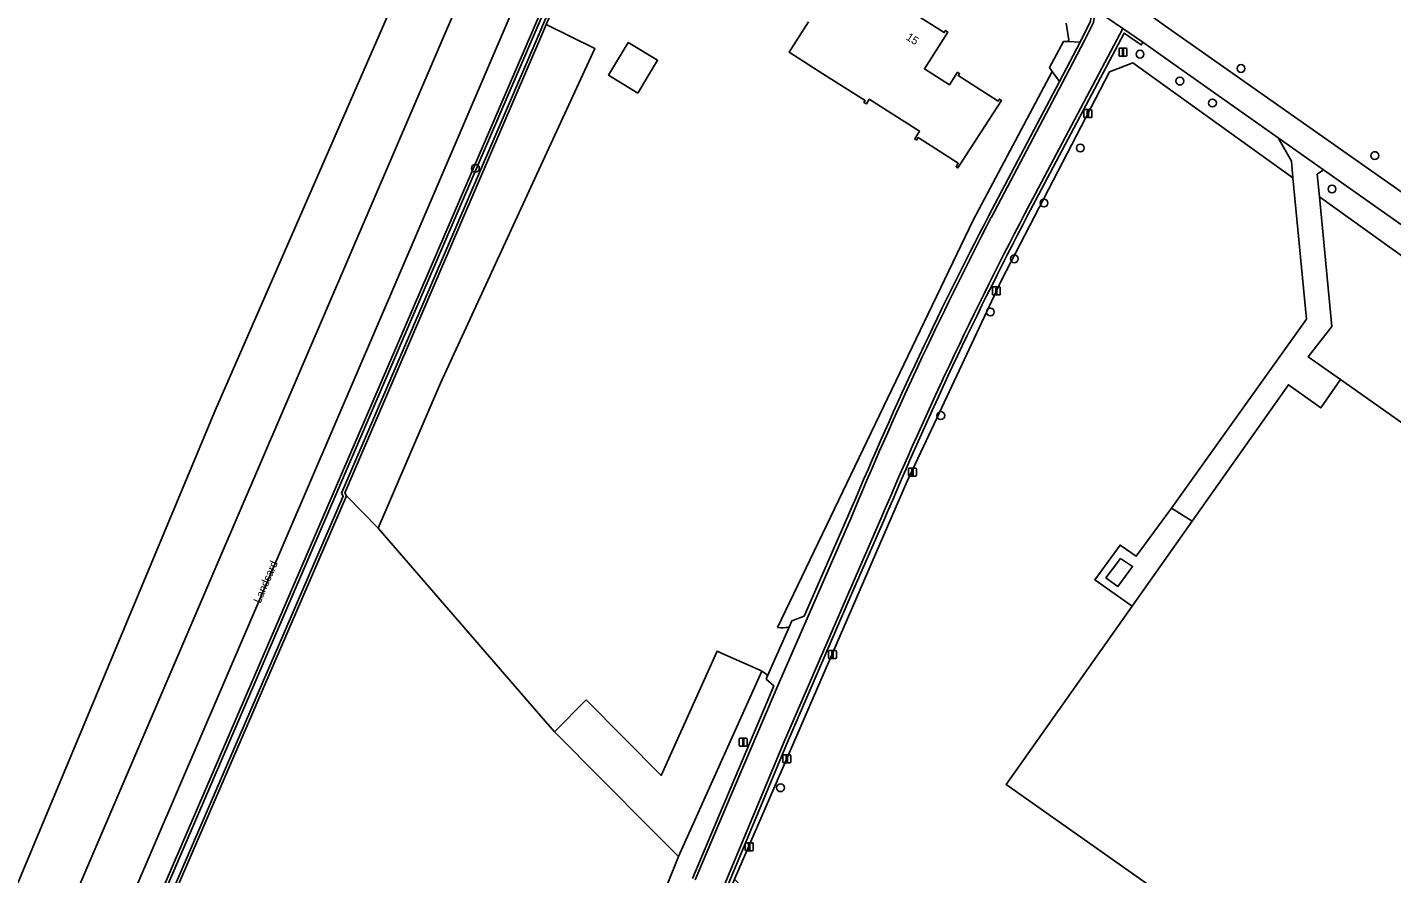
# Model space of a CAD drawing. Extents: x 155209 to 156748, y 385356 to 388487.
# Drawn here: x 155935.8 to 156106.4, y 386038.3 to 386144.1 of the extents above; entities that cross this region are included whole.
import ezdxf

# ---------------------------------------------------------------- set-up
doc = ezdxf.new("R2010")
doc.units = 0
for name, color, linetype in [('IMGEO_Berm_groen', 7, 'Continuous'), ('IMGEO_Berm_open', 7, 'Continuous'), ('IMGEO_Boom', 7, 'Continuous'), ('IMGEO_Erf', 7, 'Continuous'), ('IMGEO_Groenvoorziening', 7, 'Continuous'), ('IMGEO_Hek', 7, 'Continuous'), ('IMGEO_Lage_trafo', 7, 'Continuous'), ('IMGEO_Lichtmast', 7, 'Continuous'), ('IMGEO_Loofbos', 7, 'Continuous'), ('IMGEO_Naaldbos', 7, 'Continuous'), ('IMGEO_Oever', 7, 'Continuous'), ('IMGEO_Openbare_ruimte_label', 7, 'Continuous'), ('IMGEO_Pand', 7, 'Continuous'), ('IMGEO_Pand_nummerreeks', 7, 'Continuous'), ('IMGEO_Parkeervlak_gesloten', 7, 'Continuous'), ('IMGEO_Rijbaan_lokaal_gesloten', 7, 'Continuous'), ('IMGEO_Rijbaan_lokaal_open', 7, 'Continuous'), ('IMGEO_Verkeersbordpaal', 7, 'Continuous'), ('IMGEO_Voetpad_halfverhard', 7, 'Continuous'), ('IMGEO_Voetpad_open', 7, 'Continuous'), ('IMGEO_Waterloop', 7, 'Continuous')]:
    doc.layers.add(name, color=color, linetype=linetype)

msp = doc.modelspace()

# ---------------------------------------------------------------- linework, layer by layer
at = {"layer": 'IMGEO_Berm_groen'}
for points in [[(156017.72, 386241.8), (155997.34, 386192.47), (155999.28, 386187.65), (155999.02, 386187.05), (155959.3, 386096.17), (155916.98, 385994.93), (155916.27, 385993.23), (155920.08, 385991.51), (155920.81, 385993.21), (155925.38, 386003.82), (155927.74, 386002.82), (155959.53, 386076.88), (155989.7, 386147.22), (156003.54, 386179.53)], [(156049.55, 386158.86), (156049.35, 386159.56), (156025.31, 386175.19), (156018.61, 386179.53), (156012.19, 386182.98), (156009.84, 386177.42), (156009.58, 386176.82), (155984.91, 386119.23), (155965.64, 386074.34), (155949.14, 386035.92), (155952.02, 386034.68), (156000, 386146)], [(156065.66, 386144.59), (156066.01, 386142.46), (156065.9, 386142.27), (156067.43, 386142.22), (156068.71, 386144.84), (156068.81, 386145.67), (156068.51, 386146.37), (156067.67, 386146.89), (156067.9, 386147.28), (156055.22, 386155.8)], [(156078.71, 386139.75), (156075.27, 386142.2), (156075.05, 386141.86), (156072.94, 386143.34), (156062.21, 386123.11)], [(156018.62, 386023.35), (156020.7, 386028.43), (156024.22, 386037.59), (156045.81, 386087.34), (156049.5, 386095.21), (156057.59, 386112.46), (156071.11, 386138.48), (156074.02, 386139.6), (156094.02, 386125.25), (156093.82, 386127.35), (156092.18, 386130.24), (156078.71, 386139.75)], [(156135.52, 386099.82), (156125.95, 386106.41), (156097.82, 386126.26), (156097.06, 386125.69), (156097.33, 386122.88), (156148.23, 386086.38)], [(156042.89, 386082.44), (156038.86, 386073.22), (156030.85, 386054.72), (156018.71, 386025.67)], [(156027.62, 386063.6), (156017.22, 386040.43), (155993.88, 385981.94), (155984.26, 385961.78), (155979.58, 385953.33), (155982.07, 385950.57), (155982.25, 385950.72)], [(156018.96, 386037.69), (156023.47, 386048.35), (156027.93, 386058.88), (156029.15, 386061.75), (156028.19, 386062.62), (156028.36, 386063)]]:
    msp.add_lwpolyline(points, dxfattribs=at)
for centre, radius, start, end in [((156497.69, 385891.37), 493.3, 151.9805, 157.2124), ((156026.48, 386061.45), 2.44, 39.5677, 61.9809)]:
    msp.add_arc(centre, radius, start, end, dxfattribs=at)
at = {"layer": 'IMGEO_Berm_open'}
for points in [[(156056.32, 386120.34), (156065.18, 386137.08), (156067.96, 386142.42), (156069.08, 386144.68), (156069.24, 386145.9), (156068.86, 386146.59), (156067.9, 386147.28), (156067.67, 386146.89), (156068.51, 386146.37), (156068.81, 386145.67), (156068.71, 386144.84), (156067.43, 386142.22), (156064.83, 386137.29), (156056, 386120.53)], [(156075.27, 386142.2), (156072.75, 386143.92), (156061.83, 386123.29)], [(156062.21, 386123.11), (156072.94, 386143.34), (156075.05, 386141.86), (156075.27, 386142.2)], [(156042.51, 386082.62), (156038.47, 386073.36), (156030.47, 386054.89), (156018.34, 386025.82)], [(156018.71, 386025.67), (156030.85, 386054.72), (156038.86, 386073.22), (156042.89, 386082.44)], [(156038.35, 386082.83), (156032.91, 386070.46), (156031.37, 386069.88), (156031.03, 386069.11), (156028.36, 386063), (156028.19, 386062.62), (156029.15, 386061.75), (156027.93, 386058.88), (156023.47, 386048.35), (156018.96, 386037.69)], [(156029.56, 386061.6), (156038.74, 386082.69)], [(156019.32, 386037.52), (156023.82, 386048.16), (156029.56, 386061.6)]]:
    msp.add_lwpolyline(points, dxfattribs=at)
for centre, radius, start, end in [((156513.1, 385884.08), 510.75, 152.0725, 157.1251), ((156497.69, 385891.37), 493.3, 151.9805, 157.2124), ((156497.11, 385891.09), 497.21, 152.5191, 157.317), ((156504.59, 385888.19), 504.82, 152.6219, 157.3392)]:
    msp.add_arc(centre, radius, start, end, dxfattribs=at)
at = {"layer": 'IMGEO_Boom'}
for centre in [(156074.9, 386140.7), (156079.88, 386137.34), (156087.53, 386138.91), (156083.96, 386134.6), (156067.44, 386128.98), (156104.25, 386128.03), (155991.83, 386126.43), (156098.9, 386123.85), (156062.9, 386122.1), (156059.19, 386115.13), (156056.2, 386108.48), (156050, 386095.54), (156029.97, 386049.03)]:
    msp.add_circle(centre, 0.489, dxfattribs=at)
at = {"layer": 'IMGEO_Erf'}
for points in [[(156045.47, 386146.54), (156050.43, 386143.39), (156050.59, 386143.64), (156050.87, 386143.46), (156047.95, 386138.87), (156051.1, 386136.88), (156052.11, 386138.44), (156052.35, 386138.26), (156052.19, 386138.03), (156057.17, 386134.82), (156057.34, 386135.08), (156057.57, 386134.92), (156052.15, 386126.49), (156051.91, 386126.63), (156052.18, 386127.07), (156047.16, 386130.28), (156046.96, 386129.97), (156046.74, 386130.11), (156047.35, 386131.07), (156041.05, 386135.06), (156040.7, 386134.49), (156040.39, 386134.68), (156040.54, 386134.91), (156035.27, 386138.26), (156031.05, 386140.94), (156033.46, 386144.75)], [(156054.04, 386119.95), (156063.93, 386138.54), (156063.57, 386139.03), (156065.32, 386142.28), (156065.9, 386142.27), (156066.01, 386142.46), (156065.66, 386144.59)], [(156000.68, 386144.39), (156006.74, 386141.43), (156000, 386126.8), (155987.48, 386099.58), (155979.68, 386081.47), (156000, 386057.99), (156001.7, 386056.03), (156005.69, 386060.01), (156015.07, 386050.58), (156022.04, 386066.11), (156023.06, 386065.65), (156027.21, 386063.79), (156027.62, 386063.6)], [(156029.6, 386069.06), (156054.04, 386119.95)], [(156028.36, 386063), (156031.03, 386069.11)]]:
    msp.add_lwpolyline(points, dxfattribs=at)
msp.add_lwpolyline([(156012.13, 386135.85), (156008.47, 386138.07), (156010.94, 386142.15), (156014.6, 386139.94)], close=True, dxfattribs=at)
for centre, radius, start, end in [((156030.19, 386072.38), 3.37, 259.8828, 284.4364), ((156026.48, 386061.45), 2.44, 39.5677, 61.9809)]:
    msp.add_arc(centre, radius, start, end, dxfattribs=at)
at = {"layer": 'IMGEO_Groenvoorziening'}
for points in [[(156064.83, 386137.29), (156063.93, 386138.54), (156054.04, 386119.95), (156029.6, 386069.06)], [(156056, 386120.53), (156064.83, 386137.29)], [(156031.03, 386069.11), (156031.37, 386069.88), (156032.91, 386070.46), (156038.35, 386082.83)]]:
    msp.add_lwpolyline(points, dxfattribs=at)
for centre, radius, start, end in [((156497.11, 385891.09), 497.21, 152.5191, 157.317), ((156030.19, 386072.38), 3.37, 259.8828, 284.4364)]:
    msp.add_arc(centre, radius, start, end, dxfattribs=at)
at = {"layer": 'IMGEO_Hek'}
for points in [[(155979.68, 386081.47), (155987.48, 386099.58), (156000, 386126.8), (156006.74, 386141.43), (156000.68, 386144.39)], [(156001.7, 386056.03), (156000, 386057.99), (155979.68, 386081.47)]]:
    msp.add_lwpolyline(points, dxfattribs=at)
at = {"layer": 'IMGEO_Lage_trafo'}
msp.add_lwpolyline([(156072.46, 386077.69), (156070.64, 386075.27), (156072.15, 386074.18), (156073.97, 386076.68)], close=True, dxfattribs=at)
at = {"layer": 'IMGEO_Lichtmast'}
for p, q in [((156067.89, 386132.87), (156067.89, 386133.67)), ((156067.89, 386133.67), (156067.89, 386132.87)), ((156067.99, 386133.77), (156068.78, 386133.77)), ((156068.78, 386133.77), (156067.99, 386133.77)), ((156068.78, 386132.77), (156067.99, 386132.77)), ((156067.99, 386132.77), (156068.78, 386132.77)), ((156068.88, 386133.67), (156068.88, 386132.87)), ((156068.88, 386132.87), (156068.88, 386133.67)), ((156056.45, 386110.71), (156056.45, 386111.51)), ((156056.45, 386111.51), (156056.45, 386110.71)), ((156056.55, 386111.61), (156057.34, 386111.61)), ((156057.34, 386111.61), (156056.55, 386111.61)), ((156057.34, 386110.61), (156056.55, 386110.61)), ((156056.55, 386110.61), (156057.34, 386110.61)), ((156057.44, 386111.51), (156057.44, 386110.71)), ((156057.44, 386110.71), (156057.44, 386111.51)), ((156045.98, 386088.06), (156045.98, 386088.86)), ((156045.98, 386088.86), (156045.98, 386088.06)), ((156046.08, 386088.96), (156046.87, 386088.96)), ((156046.87, 386088.96), (156046.08, 386088.96)), ((156046.97, 386088.86), (156046.97, 386088.06)), ((156046.97, 386088.06), (156046.97, 386088.86)), ((156046.87, 386087.96), (156046.08, 386087.96)), ((156046.08, 386087.96), (156046.87, 386087.96)), ((156036.08, 386066.19), (156036.87, 386066.19)), ((156036.87, 386066.19), (156036.08, 386066.19)), ((156035.98, 386065.29), (156035.98, 386066.09)), ((156035.98, 386066.09), (156035.98, 386065.29)), ((156036.87, 386065.19), (156036.08, 386065.19)), ((156036.08, 386065.19), (156036.87, 386065.19)), ((156036.97, 386066.09), (156036.97, 386065.29)), ((156036.97, 386065.29), (156036.97, 386066.09)), ((156025.55, 386041.26), (156025.55, 386042.06)), ((156025.55, 386042.06), (156025.55, 386041.26)), ((156025.65, 386042.16), (156026.44, 386042.16)), ((156026.44, 386042.16), (156025.65, 386042.16)), ((156026.44, 386041.16), (156025.65, 386041.16)), ((156025.65, 386041.16), (156026.44, 386041.16)), ((156026.54, 386042.06), (156026.54, 386041.26)), ((156026.54, 386041.26), (156026.54, 386042.06))]:
    msp.add_line(p, q, dxfattribs=at)
for points in [[(156068.31, 386133.64), (156068.46, 386133.64), (156068.46, 386132.89), (156068.31, 386132.89), (156068.31, 386133.64)], [(156056.87, 386111.48), (156057.02, 386111.48), (156057.02, 386110.73), (156056.87, 386110.73), (156056.87, 386111.48)], [(156046.4, 386088.83), (156046.55, 386088.83), (156046.55, 386088.08), (156046.4, 386088.08), (156046.4, 386088.83)], [(156036.4, 386066.07), (156036.55, 386066.07), (156036.55, 386065.32), (156036.4, 386065.32), (156036.4, 386066.07)], [(156025.97, 386042.03), (156026.12, 386042.03), (156026.12, 386041.28), (156025.97, 386041.28), (156025.97, 386042.03)]]:
    msp.add_lwpolyline(points, dxfattribs=at)
for centre, start, end in [((156067.99, 386133.67), 90, 180), ((156067.99, 386133.67), 90, 180), ((156067.99, 386132.87), 180, 270), ((156067.99, 386132.87), 180, 270), ((156068.78, 386133.67), 0, 90), ((156068.78, 386133.67), 360, 90), ((156068.78, 386132.87), 270, 0), ((156068.78, 386132.87), 270, 0), ((156056.55, 386111.51), 90, 180), ((156056.55, 386111.51), 90, 180), ((156056.55, 386110.71), 180, 270), ((156056.55, 386110.71), 180, 270), ((156057.34, 386111.51), 0, 90), ((156057.34, 386111.51), 360, 90), ((156057.34, 386110.71), 270, 0), ((156057.34, 386110.71), 270, 0), ((156046.08, 386088.86), 90, 180), ((156046.08, 386088.86), 90, 180), ((156046.87, 386088.86), 0, 90), ((156046.87, 386088.86), 360, 90), ((156046.08, 386088.06), 180, 270), ((156046.08, 386088.06), 180, 270), ((156046.87, 386088.06), 270, 0), ((156046.87, 386088.06), 270, 0), ((156036.08, 386066.09), 90, 180), ((156036.08, 386066.09), 90, 180), ((156036.87, 386066.09), 0, 90), ((156036.87, 386066.09), 360, 90), ((156036.08, 386065.29), 180, 270), ((156036.08, 386065.29), 180, 270), ((156036.87, 386065.29), 270, 0), ((156036.87, 386065.29), 270, 0), ((156025.65, 386042.06), 90, 180), ((156025.65, 386042.06), 90, 180), ((156025.65, 386041.26), 180, 270), ((156025.65, 386041.26), 180, 270), ((156026.44, 386042.06), 0, 90), ((156026.44, 386042.06), 360, 90), ((156026.44, 386041.26), 270, 0), ((156026.44, 386041.26), 270, 0)]:
    msp.add_arc(centre, 0.1, start, end, dxfattribs=at)
at = {"layer": 'IMGEO_Loofbos'}
for points in [[(155886.19, 386008.74), (155905.67, 386000), (155916.98, 385994.93), (155959.3, 386096.17), (155999.02, 386187.05)], [(156074.43, 386077.96), (156078.82, 386083.96), (156095.72, 386107.6), (156094.02, 386125.25), (156074.02, 386139.6), (156071.11, 386138.48), (156057.59, 386112.46), (156049.5, 386095.21), (156045.81, 386087.34), (156024.22, 386037.59), (156068.01, 385994.76)], [(156097.33, 386122.88), (156098.87, 386106.67), (156095.93, 386102.88), (156099.96, 386100.04), (156160, 386057.7), (156157.51, 386054.17), (156161.54, 386051.34), (156165.11, 386056), (156179.96, 386045.42), (156184.53, 386042.68)], [(156199, 386045.66), (156201.61, 386049.59), (156176.6, 386066.75), (156171.78, 386070.1), (156148.23, 386086.38), (156097.33, 386122.88)], [(156073.82, 385996.24), (156088.77, 386017.23), (156094.05, 386024.14), (156058.17, 386049.45), (156073.91, 386071.73), (156069.27, 386075.01), (156072.41, 386079.35), (156074.43, 386077.96)]]:
    msp.add_lwpolyline(points, dxfattribs=at)
msp.add_lwpolyline([(156086.24, 386160.94), (156083.54, 386162.84), (156082.84, 386161.53), (156081.65, 386159.3), (156074.85, 386146.49), (156076.42, 386145.39), (156078.08, 386144.22), (156148.48, 386094.74), (156151.39, 386092.68), (156153.85, 386090.94), (156156.71, 386094.13), (156162.57, 386100.65), (156166.86, 386105.42), (156156.69, 386112.43), (156153.6, 386114.56), (156143.24, 386121.7)], close=True, dxfattribs=at)
at = {"layer": 'IMGEO_Naaldbos'}
for points in [[(155979.68, 386081.47), (155987.48, 386099.58), (156000, 386126.8), (156006.74, 386141.43), (156000.68, 386144.39), (156000, 386142.83), (155975.49, 386085.88), (155975.71, 386085.5)], [(156017.22, 386040.43), (156013.69, 386043.98), (156001.7, 386056.03), (156000, 386057.99), (155979.68, 386081.47), (155975.71, 386085.5), (155942.72, 386009.19), (155954.43, 385995.3), (155953.35, 385987.2), (155960.31, 385985.94), (155960.31, 385979.29), (155965.05, 385976.04), (155970.69, 385967), (155976.88, 385963.96), (155978.47, 385960.03), (155979.58, 385953.33), (155984.26, 385961.78), (155993.88, 385981.94)]]:
    msp.add_lwpolyline(points, close=True, dxfattribs=at)
at = {"layer": 'IMGEO_Oever'}
for points in [[(156015.54, 386179.18), (156015.76, 386179.19), (156015.84, 386179.15), (156015.91, 386178.56), (156028.73, 386169.96), (156048.81, 386156.86), (156048.58, 386156.51), (156048.41, 386156.24), (156033.05, 386166.23), (156015.52, 386177.85), (156015.03, 386177.92), (156014.67, 386177.6), (156000.35, 386144.53), (155999.67, 386142.97), (155975.09, 386085.85), (155975.31, 386085.48), (155942.79, 386010.26)], [(156000, 386142.83), (156000.68, 386144.39), (156014.96, 386177.38), (156015.15, 386177.54), (156015.39, 386177.51), (156032.85, 386165.93), (156048.52, 386155.74), (156048.89, 386156.32), (156049.3, 386156.97), (156028.93, 386170.26), (156016.25, 386178.76), (156016.17, 386179.38), (156015.84, 386179.55), (156015.47, 386179.53)], [(156013.5, 386177.7), (156000, 386146), (155952.02, 386034.68), (155941.6, 386010.52), (155942.72, 386009.19), (155975.71, 386085.5), (155975.49, 386085.88), (156000, 386142.83)], [(155942.79, 386010.26), (155942.16, 386010.92), (156000.33, 386145.86), (156013.83, 386177.55)]]:
    msp.add_lwpolyline(points, dxfattribs=at)
at = {"layer": 'IMGEO_Pand'}
msp.add_lwpolyline([(156033.46, 386144.75), (156031.05, 386140.94), (156035.27, 386138.26), (156040.54, 386134.91), (156040.39, 386134.68), (156040.7, 386134.49), (156041.05, 386135.06), (156047.35, 386131.07), (156046.74, 386130.11), (156046.96, 386129.97), (156047.16, 386130.28), (156052.18, 386127.07), (156051.91, 386126.63), (156052.15, 386126.49), (156057.57, 386134.92), (156057.34, 386135.08), (156057.17, 386134.82), (156052.19, 386138.03), (156052.35, 386138.26), (156052.11, 386138.44), (156051.1, 386136.88), (156047.95, 386138.87), (156050.87, 386143.46), (156050.59, 386143.64), (156050.43, 386143.39), (156045.47, 386146.54)], dxfattribs=at)
for points in [[(156012.13, 386135.85), (156014.6, 386139.94), (156010.94, 386142.15), (156008.47, 386138.07)], [(156023.06, 386065.65), (156022.04, 386066.11), (156015.07, 386050.58), (156005.69, 386060.01), (156001.7, 386056.03), (156013.69, 386043.98), (156017.22, 386040.43), (156027.62, 386063.6), (156027.21, 386063.79)]]:
    msp.add_lwpolyline(points, close=True, dxfattribs=at)
at = {"layer": 'IMGEO_Parkeervlak_gesloten'}
msp.add_lwpolyline([(156160, 386057.7), (156099.96, 386100.04), (156097.49, 386096.49), (156093.46, 386099.39), (156081.42, 386082.36), (156073.91, 386071.73), (156058.17, 386049.45), (156094.05, 386024.14), (156103.89, 386017.19), (156126.19, 386001.46), (156126.3, 386001.39), (156154.84, 386041.84), (156161.54, 386051.34), (156157.51, 386054.17)], close=True, dxfattribs=at)
at = {"layer": 'IMGEO_Rijbaan_lokaal_gesloten'}
for points in [[(155944.24, 386024.53), (155949.14, 386035.92), (155965.64, 386074.34), (155984.91, 386119.23), (156009.58, 386176.82), (156003.54, 386179.53), (155989.7, 386147.22), (155959.53, 386076.88), (155927.74, 386002.82), (155923, 385991.79), (155918.96, 385982.46), (155913.39, 385969.48), (155908.98, 385959.23), (155875.91, 385882.64)], [(156061.83, 386123.29), (156072.75, 386143.92), (156068.86, 386146.59), (156069.24, 386145.9), (156069.08, 386144.68), (156067.96, 386142.42), (156065.18, 386137.08), (156056.32, 386120.34)], [(156068.86, 386146.59), (156072.75, 386143.92), (156075.27, 386142.2), (156078.71, 386139.75), (156092.18, 386130.24), (156097.82, 386126.26), (156125.95, 386106.41)], [(156148.48, 386094.74), (156078.08, 386144.22)], [(156018.34, 386025.82), (156030.47, 386054.89), (156038.47, 386073.36), (156042.51, 386082.62)], [(156038.74, 386082.69), (156029.56, 386061.6), (156023.82, 386048.16), (156019.32, 386037.52)]]:
    msp.add_lwpolyline(points, dxfattribs=at)
for centre, radius, start, end in [((156513.1, 385884.08), 510.75, 152.0725, 157.1251), ((156504.59, 385888.19), 504.82, 152.6219, 157.3392)]:
    msp.add_arc(centre, radius, start, end, dxfattribs=at)
at = {"layer": 'IMGEO_Rijbaan_lokaal_open'}
msp.add_lwpolyline([(156067.43, 386142.22), (156065.9, 386142.27), (156065.32, 386142.28), (156063.57, 386139.03), (156063.93, 386138.54), (156064.83, 386137.29)], close=True, dxfattribs=at)
at = {"layer": 'IMGEO_Verkeersbordpaal'}
for p, q in [((156072.28, 386140.55), (156072.28, 386141.35)), ((156072.28, 386141.35), (156072.28, 386140.55)), ((156072.38, 386141.45), (156073.17, 386141.45)), ((156073.17, 386141.45), (156072.38, 386141.45)), ((156073.27, 386141.35), (156073.27, 386140.55)), ((156073.27, 386140.55), (156073.27, 386141.35)), ((156073.17, 386140.45), (156072.38, 386140.45)), ((156072.38, 386140.45), (156073.17, 386140.45)), ((156024.82, 386054.33), (156024.82, 386055.13)), ((156024.82, 386055.13), (156024.82, 386054.33)), ((156024.92, 386055.23), (156025.7, 386055.23)), ((156025.7, 386055.23), (156024.92, 386055.23)), ((156025.7, 386054.23), (156024.92, 386054.23)), ((156024.92, 386054.23), (156025.7, 386054.23)), ((156025.8, 386055.13), (156025.8, 386054.33)), ((156025.8, 386054.33), (156025.8, 386055.13)), ((156030.26, 386052.25), (156030.26, 386053.05)), ((156030.26, 386053.05), (156030.26, 386052.25)), ((156030.36, 386053.15), (156031.15, 386053.15)), ((156031.15, 386053.15), (156030.36, 386053.15)), ((156031.25, 386053.05), (156031.25, 386052.25)), ((156031.25, 386052.25), (156031.25, 386053.05)), ((156031.15, 386052.15), (156030.36, 386052.15)), ((156030.36, 386052.15), (156031.15, 386052.15))]:
    msp.add_line(p, q, dxfattribs=at)
for points in [[(156072.7, 386141.32), (156072.85, 386141.32), (156072.85, 386140.57), (156072.7, 386140.57), (156072.7, 386141.32)], [(156025.24, 386055.1), (156025.39, 386055.1), (156025.39, 386054.35), (156025.24, 386054.35), (156025.24, 386055.1)], [(156030.68, 386053.03), (156030.83, 386053.03), (156030.83, 386052.28), (156030.68, 386052.28), (156030.68, 386053.03)]]:
    msp.add_lwpolyline(points, dxfattribs=at)
for centre, start, end in [((156072.38, 386141.35), 90, 180), ((156072.38, 386141.35), 90, 180), ((156073.17, 386141.35), 0, 90), ((156073.17, 386141.35), 360, 90), ((156072.38, 386140.55), 180, 270), ((156072.38, 386140.55), 180, 270), ((156073.17, 386140.55), 270, 0), ((156073.17, 386140.55), 270, 0), ((156024.92, 386055.13), 90, 180), ((156024.92, 386055.13), 90, 180), ((156024.92, 386054.33), 180, 270), ((156024.92, 386054.33), 180, 270), ((156025.7, 386055.13), 0, 90), ((156025.7, 386055.13), 360, 90), ((156025.7, 386054.33), 270, 0), ((156025.7, 386054.33), 270, 0), ((156030.36, 386053.05), 90, 180), ((156030.36, 386053.05), 90, 180), ((156031.15, 386053.05), 0, 90), ((156031.15, 386053.05), 360, 90), ((156030.36, 386052.25), 180, 270), ((156030.36, 386052.25), 180, 270), ((156031.15, 386052.25), 270, 0), ((156031.15, 386052.25), 270, 0)]:
    msp.add_arc(centre, 0.1, start, end, dxfattribs=at)
at = {"layer": 'IMGEO_Voetpad_halfverhard'}
for points in [[(156081.42, 386082.36), (156079.03, 386083.83), (156078.82, 386083.96), (156074.43, 386077.96), (156072.41, 386079.35), (156069.27, 386075.01), (156073.91, 386071.73)], [(156072.46, 386077.69), (156073.97, 386076.68), (156072.15, 386074.18), (156070.64, 386075.27)]]:
    msp.add_lwpolyline(points, close=True, dxfattribs=at)
at = {"layer": 'IMGEO_Voetpad_open'}
msp.add_lwpolyline([(156097.33, 386122.88), (156097.06, 386125.69), (156097.82, 386126.26), (156092.18, 386130.24), (156093.82, 386127.35), (156094.02, 386125.25), (156095.72, 386107.6), (156078.82, 386083.96), (156079.03, 386083.83), (156081.42, 386082.36), (156093.46, 386099.39), (156097.49, 386096.49), (156099.96, 386100.04), (156095.93, 386102.88), (156098.87, 386106.67)], close=True, dxfattribs=at)
at = {"layer": 'IMGEO_Waterloop'}
msp.add_lwpolyline([(156013.83, 386177.55), (156000.33, 386145.86), (155942.16, 386010.92), (155942.79, 386010.26), (155975.31, 386085.48), (155975.09, 386085.85), (155999.67, 386142.97), (156000.35, 386144.53), (156014.67, 386177.6), (156015.03, 386177.92), (156015.52, 386177.85), (156033.05, 386166.23), (156048.41, 386156.24), (156048.58, 386156.51), (156048.81, 386156.86), (156028.73, 386169.96), (156015.91, 386178.56), (156015.84, 386179.15), (156015.76, 386179.19), (156015.54, 386179.18)], dxfattribs=at)

# ---------------------------------------------------------------- texts
at = {"layer": 'IMGEO_Openbare_ruimte_label'}
msp.add_text('Landsard', height=1, rotation=66.666, dxfattribs=at).set_placement((155964.95, 386072))
at = {"layer": 'IMGEO_Pand_nummerreeks'}
msp.add_text('15', height=1, rotation=327.605, dxfattribs=at).set_placement((156045.57, 386142.59))

doc.saveas('drawing.dxf')
